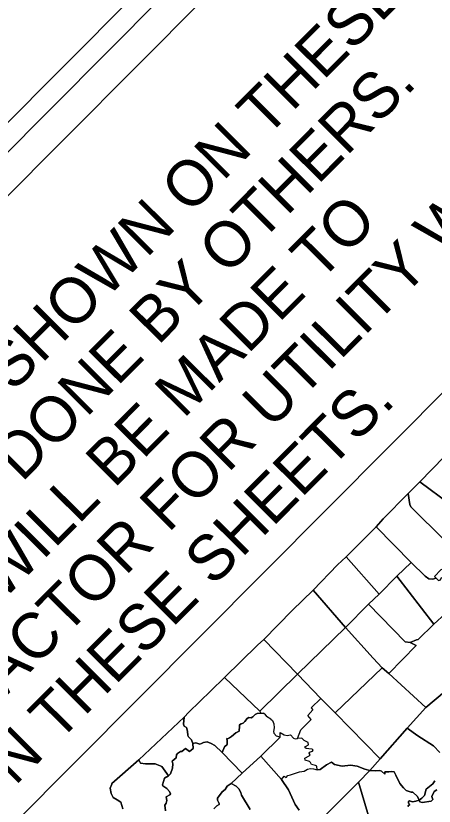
# Model space of a CAD drawing. Extents: x 1484850 to 1495577, y 495475 to 506245.
# Drawn here: x 1488420 to 1488695, y 500537 to 501057 of the extents above; entities that cross this region are included whole.
import ezdxf

# ---------------------------------------------------------------- set-up
doc = ezdxf.new("R2010")
doc.units = 0
doc.layers.add('Default', color=7, linetype='Continuous')
doc.layers.add('Exist Utilities Power UG Cable SUE LOS C', color=7, linetype='Continuous')

msp = doc.modelspace()

# ---------------------------------------------------------------- linework, layer by layer
at = {"layer": 'Default'}
for p, q in [((1488605.27, 500623.53), (1488636.94, 500654.32)), ((1488636.94, 500654.32), (1488655.25, 500634.15)), ((1488578.98, 500642.65), (1488583.08, 500646.27)), ((1488583.08, 500646.27), (1488605.27, 500623.53)), ((1488557.37, 500621.25), (1488578.98, 500642.65)), ((1488655.25, 500634.15), (1488661.2, 500627.78)), ((1488580.53, 500599.25), (1488605.27, 500623.53)), ((1488620.65, 500607.41), (1488605.27, 500623.53)), ((1488661.2, 500627.78), (1488630.24, 500597.97)), ((1488580.53, 500599.25), (1488557.37, 500621.25)), ((1488620.65, 500607.41), (1488614.47, 500601.36)), ((1488620.65, 500607.41), (1488630.24, 500597.97)), ((1488630.24, 500597.97), (1488620.65, 500607.41)), ((1488575.83, 500595.45), (1488577.43, 500596.94)), ((1488577.43, 500596.94), (1488578.83, 500597.69)), ((1488578.83, 500597.69), (1488581.26, 500597.86)), ((1488581.26, 500597.86), (1488582.79, 500597.82)), ((1488583.88, 500597.15), (1488582.79, 500597.82)), ((1488583.88, 500597.15), (1488584.94, 500595.71)), ((1488615.53, 500599.93), (1488612.12, 500596.22)), ((1488614.47, 500601.36), (1488615.53, 500599.93)), ((1488630.24, 500597.97), (1488659.88, 500567.83)), ((1488569.62, 500591.25), (1488570.64, 500592.31)), ((1488570.64, 500592.31), (1488572.24, 500594.4)), ((1488572.24, 500594.4), (1488573.35, 500594.93)), ((1488573.35, 500594.93), (1488574.79, 500594.82)), ((1488574.79, 500594.82), (1488575.83, 500595.45)), ((1488587.72, 500593.78), (1488584.94, 500595.71)), ((1488587.72, 500593.78), (1488588.89, 500593.01)), ((1488588.89, 500593.01), (1488589.81, 500590.74)), ((1488614.28, 500593.69), (1488607.56, 500586.78)), ((1488614.28, 500593.69), (1488612.12, 500596.22)), ((1488566.92, 500585.96), (1488567.24, 500589.18)), ((1488567.23, 500590.21), (1488568.34, 500590.74)), ((1488567.24, 500589.18), (1488567.23, 500590.21)), ((1488568.34, 500590.74), (1488569.62, 500591.25)), ((1488590.09, 500588.13), (1488589.56, 500585.81)), ((1488589.81, 500590.74), (1488590.09, 500588.13)), ((1488605.47, 500581.09), (1488607.56, 500586.78)), ((1488559.31, 500581), (1488560.68, 500581.59)), ((1488560.68, 500581.59), (1488561.17, 500581.95)), ((1488561.17, 500581.95), (1488561.84, 500582.46)), ((1488561.84, 500582.46), (1488564.7, 500584.89)), ((1488564.7, 500584.89), (1488566.92, 500585.96)), ((1488593.84, 500582.04), (1488581.14, 500569.43)), ((1488589.56, 500585.81), (1488589.81, 500584.66)), ((1488589.81, 500584.66), (1488591.62, 500582.61)), ((1488593.84, 500582.04), (1488591.62, 500582.61)), ((1488593.84, 500582.04), (1488593.98, 500585.1)), ((1488593.98, 500585.1), (1488596.47, 500583.55)), ((1488596.47, 500583.55), (1488598.54, 500583.18)), ((1488598.54, 500583.18), (1488600.72, 500583.47)), ((1488600.72, 500583.47), (1488602.77, 500581.3)), ((1488602.77, 500581.3), (1488603.75, 500580.99)), ((1488608.18, 500581.47), (1488605.47, 500581.09)), ((1488609.8, 500579.88), (1488608.18, 500581.47)), ((1488557.29, 500575.62), (1488558.99, 500577.19)), ((1488558.94, 500579.68), (1488558.81, 500581.07)), ((1488558.81, 500581.07), (1488559.31, 500581)), ((1488558.99, 500577.19), (1488558.94, 500579.68)), ((1488603.75, 500580.99), (1488605.47, 500581.09)), ((1488612.48, 500578.47), (1488609.8, 500579.88)), ((1488610.7, 500575.82), (1488612.6, 500577.09)), ((1488612.6, 500577.09), (1488612.48, 500578.47)), ((1488555.8, 500571.96), (1488557.29, 500575.62)), ((1488568.95, 500558.36), (1488555.8, 500571.96)), ((1488610.19, 500575.29), (1488610.7, 500575.82)), ((1488611.09, 500574.48), (1488610.19, 500575.29)), ((1488612.76, 500574.25), (1488611.09, 500574.48)), ((1488615.12, 500574.08), (1488612.76, 500574.25)), ((1488613.1, 500571.55), (1488613.18, 500572.05)), ((1488613.61, 500570.45), (1488613.1, 500571.55)), ((1488613.18, 500572.05), (1488615.17, 500572.79)), ((1488615.61, 500573.42), (1488615.12, 500574.08)), ((1488615.17, 500572.79), (1488615.61, 500573.42)), ((1488581.14, 500569.43), (1488568.95, 500558.36)), ((1488610.1, 500568.13), (1488612.98, 500569.69)), ((1488610.51, 500566.96), (1488610.1, 500568.13)), ((1488613.34, 500565.97), (1488610.51, 500566.96)), ((1488612.98, 500569.69), (1488613.61, 500570.45)), ((1488613.83, 500565.3), (1488613.34, 500565.97)), ((1488659.88, 500567.83), (1488653.05, 500560.15)), ((1488614.65, 500563.99), (1488613.83, 500565.3)), ((1488617.29, 500563.45), (1488614.65, 500563.99)), ((1488618.04, 500562.83), (1488617.29, 500563.45)), ((1488618.27, 500560.5), (1488618.04, 500562.83)), ((1488620.28, 500560.81), (1488618.27, 500560.5)), ((1488624.49, 500563.8), (1488620.28, 500560.81)), ((1488627.66, 500565.56), (1488624.49, 500563.8)), ((1488629.64, 500564.09), (1488627.66, 500565.56)), ((1488634.81, 500562.93), (1488629.64, 500564.09)), ((1488640.17, 500563.52), (1488634.81, 500562.93)), ((1488644.59, 500562.98), (1488640.17, 500563.52)), ((1488649.72, 500561.05), (1488644.59, 500562.98)), ((1488653.05, 500560.15), (1488649.72, 500561.05))]:
    msp.add_line(p, q, dxfattribs=at)
for points in [[(1488702.04, 500766.61), (1488710.77, 500775.7), (1488713.28, 500773.38), (1488718.32, 500768.46), (1488723.84, 500762.87), (1488728.78, 500754.1), (1488730.52, 500749.07), (1488731.94, 500743.66), (1488728.45, 500743.38), (1488723.43, 500739.4), (1488721.89, 500738.45), (1488720.28, 500739.06), (1488719.09, 500738.65), (1488717.36, 500737.13), (1488712.6, 500733.61), (1488709.76, 500730.71), (1488708.92, 500730.85), (1488707.09, 500729.26), (1488706.43, 500734.19), (1488705.5, 500735.72), (1488685.87, 500750.16), (1488702.04, 500766.61)], [(1488702.04, 500766.61), (1488685.87, 500750.16), (1488678.28, 500742.4), (1488661.76, 500725.88), (1488657.14, 500720.65), (1488637.36, 500700.77), (1488631.73, 500695.51), (1488615.67, 500678.8), (1488601.94, 500665.5), (1488583.08, 500646.27), (1488578.98, 500642.65), (1488557.37, 500621.25), (1488548.28, 500612.52), (1488533.83, 500598.41), (1488530.77, 500595.21), (1488500.91, 500567.08), (1488483.02, 500551.49), (1488483.05, 500551.06), (1488481.91, 500548.54), (1488482.52, 500544.93), (1488484.03, 500542.33), (1488486.56, 500540.81), (1488488.89, 500539.14), (1488490.34, 500534.84)], [(1488707.09, 500729.26), (1488708.3, 500725.44), (1488705.67, 500722.25), (1488708.4, 500715.87), (1488702.41, 500711.6), (1488679.94, 500733.76), (1488679.34, 500735.24), (1488678.28, 500742.4), (1488685.87, 500750.16), (1488705.5, 500735.72), (1488706.43, 500734.19), (1488707.09, 500729.26)], [(1488678.28, 500742.4), (1488679.34, 500735.24), (1488679.94, 500733.76), (1488702.41, 500711.6), (1488705.26, 500708.81), (1488706.13, 500706.95), (1488708.92, 500700.92), (1488710.89, 500700.43), (1488712.85, 500697.45), (1488699.86, 500692.24), (1488695.65, 500687.76), (1488696.74, 500686.64), (1488694.24, 500686.01), (1488691.87, 500686.21), (1488689.47, 500688.14), (1488680.3, 500697.07), (1488657.14, 500720.65), (1488661.76, 500725.88), (1488678.28, 500742.4)], [(1488637.36, 500700.77), (1488657.14, 500720.65), (1488680.3, 500697.07), (1488670.68, 500688.09), (1488659.06, 500676.31), (1488637.36, 500700.77)], [(1488637.36, 500700.77), (1488659.06, 500676.31), (1488652.2, 500669.71), (1488636.94, 500654.32), (1488615.67, 500678.8), (1488631.73, 500695.51), (1488637.36, 500700.77)], [(1488670.68, 500688.09), (1488680.3, 500697.07), (1488689.47, 500688.14), (1488691.87, 500686.21), (1488694.24, 500686.01), (1488696.74, 500686.64), (1488698.3, 500685.27), (1488699.49, 500685.69), (1488700.25, 500687.11), (1488701.57, 500687.33), (1488703.43, 500685.74), (1488705.04, 500683.69), (1488706.17, 500679.82), (1488705.99, 500676.33), (1488703.32, 500674.27), (1488706.12, 500667.23), (1488702.84, 500663.56), (1488695.14, 500656.55), (1488670.68, 500688.09)], [(1488659.06, 500676.31), (1488670.68, 500688.09), (1488695.14, 500656.55), (1488684.8, 500646.43), (1488683.81, 500646.15), (1488679.59, 500644.4), (1488676.17, 500644.85), (1488652.2, 500669.71), (1488659.06, 500676.31)], [(1488601.94, 500665.5), (1488615.67, 500678.8), (1488636.94, 500654.32), (1488605.27, 500623.53), (1488583.08, 500646.27), (1488601.94, 500665.5)], [(1488679.59, 500644.4), (1488681.71, 500643.31), (1488683.53, 500642.43), (1488665.53, 500624.05), (1488661.2, 500627.78), (1488655.25, 500634.15), (1488636.94, 500654.32), (1488652.2, 500669.71), (1488676.17, 500644.85), (1488679.59, 500644.4)], [(1488702.14, 500611.83), (1488689.81, 500601.53), (1488665.53, 500624.05), (1488683.53, 500642.43), (1488681.71, 500643.31), (1488679.59, 500644.4), (1488683.81, 500646.15), (1488684.8, 500646.43), (1488695.14, 500656.55), (1488702.84, 500663.56)], [(1488665.53, 500624.05), (1488689.81, 500601.53), (1488677.64, 500587.94), (1488659.88, 500567.83), (1488630.24, 500597.97), (1488661.2, 500627.78), (1488665.53, 500624.05)], [(1488580.53, 500599.25), (1488581.26, 500597.86), (1488578.83, 500597.69), (1488577.43, 500596.94), (1488575.83, 500595.45), (1488574.79, 500594.82), (1488573.35, 500594.93), (1488572.24, 500594.4), (1488570.64, 500592.31), (1488569.62, 500591.25), (1488568.34, 500590.74), (1488567.23, 500590.21), (1488567.24, 500589.18), (1488566.92, 500585.96), (1488564.7, 500584.89), (1488561.84, 500582.46), (1488561.17, 500581.95), (1488560.68, 500581.59), (1488559.31, 500581), (1488558.81, 500581.07), (1488558.94, 500579.68), (1488558.99, 500577.19), (1488557.29, 500575.62), (1488555.8, 500571.96), (1488550.85, 500576.58), (1488548.56, 500577.84), (1488545.8, 500578.9), (1488543.45, 500578.61), (1488542.22, 500577.84), (1488540.94, 500577.32), (1488538.42, 500578.26), (1488536.31, 500577.86), (1488535.48, 500580.38), (1488533.53, 500582.19), (1488533.05, 500583.03), (1488532.81, 500585.98), (1488532.16, 500588.48), (1488530.75, 500589.36), (1488530.32, 500590.53), (1488530.77, 500595.21), (1488533.83, 500598.41), (1488548.28, 500612.52), (1488557.37, 500621.25), (1488580.53, 500599.25)], [(1488699.12, 500571.99), (1488694.99, 500576.26), (1488684.64, 500582.99), (1488677.64, 500587.94), (1488689.81, 500601.53), (1488702.14, 500611.83)], [(1488530.77, 500595.21), (1488530.32, 500590.53), (1488530.75, 500589.36), (1488532.16, 500588.48), (1488532.81, 500585.98), (1488533.05, 500583.03), (1488533.53, 500582.19), (1488535.48, 500580.38), (1488536.31, 500577.86), (1488536.67, 500574.55), (1488534.32, 500572.63), (1488531.52, 500574.55), (1488529.18, 500572.63), (1488528.31, 500572.57), (1488526.41, 500571.28), (1488525.58, 500570.36), (1488525.38, 500568.41), (1488522.82, 500566.18), (1488523.24, 500564.4), (1488523.01, 500561.68), (1488521.67, 500557.83), (1488520.37, 500556.54), (1488515.98, 500562.78), (1488513.86, 500563.58), (1488511.68, 500564.46), (1488505.23, 500564.36), (1488501.86, 500564.8), (1488500.91, 500567.08), (1488530.77, 500595.21)], [(1488659.88, 500567.83), (1488677.64, 500587.94), (1488684.64, 500582.99), (1488694.99, 500576.26), (1488699.12, 500571.99)], [(1488518.47, 500533.55), (1488517.88, 500537.14), (1488518.84, 500538.47), (1488519.28, 500540.3), (1488518.86, 500542.67), (1488521.36, 500543.97), (1488521.81, 500544.77), (1488521.1, 500546.32), (1488519.4, 500548.17), (1488516.6, 500550.08), (1488516.34, 500550.63), (1488517.65, 500554.92), (1488520.37, 500556.54), (1488521.67, 500557.83), (1488523.01, 500561.68), (1488523.24, 500564.4), (1488522.82, 500566.18), (1488525.38, 500568.41), (1488525.58, 500570.36), (1488526.41, 500571.28), (1488528.31, 500572.57), (1488529.18, 500572.63), (1488531.52, 500574.55), (1488534.32, 500572.63), (1488536.67, 500574.55), (1488536.31, 500577.86)], [(1488536.31, 500577.86), (1488538.42, 500578.26), (1488540.94, 500577.32), (1488542.22, 500577.84), (1488543.45, 500578.61), (1488545.8, 500578.9), (1488548.56, 500577.84), (1488550.85, 500576.58), (1488555.8, 500571.96), (1488568.95, 500558.36), (1488561.6, 500551.48), (1488559.03, 500549.69), (1488557.67, 500547.48), (1488555.68, 500546.12), (1488552.73, 500541.81), (1488552.7, 500540.44), (1488553.84, 500538.33), (1488553.67, 500537.75), (1488552.25, 500536.83), (1488550.33, 500534.78)], [(1488490.34, 500534.84), (1488488.89, 500539.14), (1488486.56, 500540.81), (1488484.03, 500542.33), (1488482.52, 500544.93), (1488481.91, 500548.54), (1488483.05, 500551.06), (1488483.02, 500551.49), (1488500.91, 500567.08)], [(1488500.91, 500567.08), (1488501.86, 500564.8), (1488505.23, 500564.36), (1488511.68, 500564.46), (1488513.86, 500563.58), (1488515.98, 500562.78), (1488520.37, 500556.54), (1488517.65, 500554.92), (1488516.34, 500550.63), (1488516.6, 500550.08), (1488519.4, 500548.17), (1488521.1, 500546.32), (1488521.81, 500544.77), (1488521.36, 500543.97), (1488518.86, 500542.67), (1488519.28, 500540.3), (1488518.84, 500538.47), (1488517.88, 500537.14), (1488518.47, 500533.55)], [(1488574.15, 500534.5), (1488568.38, 500543.81), (1488568.04, 500545.48), (1488566.62, 500547.98), (1488565.01, 500549.74), (1488561.6, 500551.48), (1488568.95, 500558.36), (1488581.14, 500569.43), (1488594.74, 500554.14)], [(1488695.91, 500553.31), (1488694.48, 500551.23), (1488690.14, 500547.89), (1488689.12, 500543.63), (1488687.25, 500541.96), (1488685.4, 500540.45), (1488684.45, 500542.96), (1488681.25, 500545.71), (1488680.26, 500545.85), (1488677.03, 500546.83), (1488675.12, 500548.63), (1488672.8, 500551.6), (1488670.19, 500556.99), (1488668.94, 500559.29), (1488667.02, 500559.49), (1488665.45, 500559.2), (1488662.91, 500559.23), (1488662.84, 500557.71), (1488660.76, 500559.54), (1488659.56, 500559.97), (1488656.73, 500559.79), (1488653.05, 500560.15), (1488659.88, 500567.83)], [(1488596.53, 500556.37), (1488598, 500555.4), (1488599.06, 500556.78), (1488600.74, 500557.15), (1488606.58, 500559.15), (1488609.71, 500559.57), (1488612.04, 500560.86), (1488613.9, 500561.37), (1488615.83, 500561.18), (1488618.27, 500560.5), (1488620.28, 500560.81), (1488624.49, 500563.8), (1488627.66, 500565.56), (1488629.64, 500564.09), (1488634.81, 500562.93), (1488640.17, 500563.52), (1488644.59, 500562.98), (1488649.72, 500561.05), (1488653.05, 500560.15), (1488645.45, 500552.31), (1488620.47, 500527.34)], [(1488606.53, 500533.85), (1488603.8, 500537.72), (1488602.63, 500540.09), (1488599.39, 500547.27), (1488594.74, 500554.14), (1488596.53, 500556.37)], [(1488656.25, 500516.17), (1488645.45, 500552.31), (1488653.05, 500560.15)], [(1488653.05, 500560.15), (1488656.73, 500559.79), (1488659.56, 500559.97), (1488660.76, 500559.54), (1488662.84, 500557.71), (1488662.91, 500559.23), (1488665.45, 500559.2), (1488667.02, 500559.49), (1488668.94, 500559.29), (1488670.19, 500556.99), (1488672.8, 500551.6), (1488675.12, 500548.63), (1488677.03, 500546.83), (1488680.26, 500545.85), (1488681.25, 500545.71), (1488684.45, 500542.96), (1488685.4, 500540.45), (1488683.29, 500539.91), (1488681.1, 500539.46), (1488679.17, 500540.08), (1488678.5, 500539.58), (1488678.51, 500538.57), (1488679.4, 500537.76), (1488678.44, 500537.05), (1488678.07, 500536.34)], [(1488550.33, 500534.78), (1488552.25, 500536.83), (1488553.67, 500537.75), (1488553.84, 500538.33), (1488552.7, 500540.44), (1488552.73, 500541.81), (1488555.68, 500546.12), (1488557.67, 500547.48), (1488559.03, 500549.69), (1488561.6, 500551.48)], [(1488561.6, 500551.48), (1488565.01, 500549.74), (1488566.62, 500547.98), (1488568.04, 500545.48), (1488568.38, 500543.81), (1488574.15, 500534.5)], [(1488594.74, 500554.14), (1488599.39, 500547.27), (1488602.63, 500540.09), (1488603.8, 500537.72), (1488606.53, 500533.85)], [(1488620.47, 500527.34), (1488645.45, 500552.31), (1488656.25, 500516.17), (1488652.38, 500513.58), (1488644.68, 500512.36), (1488641.6, 500512.11), (1488634.99, 500517.01), (1488627.23, 500516.64), (1488618.82, 500520.94), (1488616.44, 500523.14), (1488620.47, 500527.34)], [(1488697.15, 500547.37), (1488695.36, 500546.19), (1488693.84, 500543.03), (1488694.44, 500540.99), (1488693.43, 500539.96), (1488687.46, 500539.05), (1488685.9, 500539.36), (1488685.4, 500540.45), (1488687.25, 500541.96), (1488689.12, 500543.63), (1488690.14, 500547.89), (1488694.48, 500551.23), (1488695.91, 500553.31)], [(1488678.51, 500538.57), (1488678.5, 500539.58), (1488679.17, 500540.08), (1488681.1, 500539.46), (1488683.29, 500539.91), (1488685.4, 500540.45), (1488685.9, 500539.36), (1488687.46, 500539.05), (1488693.43, 500539.96), (1488694.44, 500540.99), (1488693.84, 500543.03), (1488695.36, 500546.19), (1488697.15, 500547.37)], [(1488678.07, 500536.34), (1488678.44, 500537.05), (1488679.4, 500537.76), (1488678.51, 500538.57)]]:
    msp.add_lwpolyline(points, dxfattribs=at)
at = {"layer": 'Exist Utilities Power UG Cable SUE LOS C'}
for p, q in [((1488063.91, 500635.07), (1488623.93, 501197.22)), ((1488082.63, 500633.83), (1488623.37, 501177.35)), ((1488637.93, 501163.12), (1488097.17, 500619.62)), ((1488305.67, 500411.72), (1488846.41, 500955.24))]:
    msp.add_line(p, q, dxfattribs=at)

# ---------------------------------------------------------------- texts
for s, p in [('ALL UTILITY WORK SHOWN ON THESE ', (1488150.67, 500540.02)), ('SHEETS WILL BE DONE BY OTHERS. ', (1488183.22, 500507.63)), ('THE CONTRACTOR FOR UTILITY WORK ', (1488248.34, 500442.85)), ('NO PAYMENT WILL BE MADE TO ', (1488215.78, 500475.24)), ('SHOWN ON THESE SHEETS.', (1488280.9, 500410.46))]:
    msp.add_text(s, height=30, rotation=45.1476, dxfattribs=at).set_placement(p)

doc.saveas('drawing.dxf')
